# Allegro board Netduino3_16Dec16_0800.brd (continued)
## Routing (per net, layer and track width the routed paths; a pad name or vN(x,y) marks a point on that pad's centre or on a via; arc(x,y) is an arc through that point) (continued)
N199051: length 8.7
  TOP w0.18: R1.2 40.75,41.99 40.88,42.13 40.9,42.13 40.9,42.55 40.31,43.14 39.81,43.14 39.5,43.45 39.1,43.45 38.6,42.95 38.6,40.7 37.7,39.8 Q4.3
N202411: length 25.5
  TOP w0.18: Q8.6 52.65,29.07 53.23,29.65 53.23,36.32 48.65,40.9 v1(42.6,40.9) ; R1.3 40.25,42.4 v1(40.1,42.55)
  BOTTOM w0.18: v1(42.6,40.9) 40.95,42.55 v1(40.1,42.55)
N203046: length 25.7
  TOP w0.18: v1(42.97,40.15) 48.85,40.15 52.65,36.35 52.65,31.95 51.35,30.65 Q8.3 ; R1.4 39.7,41.55 39.33,41.92 39.33,42.17 39.3,42.2 v1(39.3,42.75)
  BOTTOM w0.18: v1(39.3,42.75) 39.69,43.14 41.21,43.14 43.15,41.2 43.15,40.34 v1(42.97,40.15)
N249435: length 34.8
  TOP w0.18: v1(38.3,20.97) 38.85,20.97 39.05,21.17 41.09,21.17 42.53,19.73 U4.48 ; R14.5 v1(30.3,38.97)
  BOTTOM w0.18: v1(30.3,38.97) 30.3,36.14 30.18,36.02 30.18,34.28 30.6,33.86 33.24,31.22 34.2,31.22 34.41,31.01 34.73,30.69 34.73,29.94 33.2,28.41 33.2,20.99 34.97,19.23 37.11,19.23 38.3,20.42 v1(38.3,20.97)
N261857: length 4.3
  TOP w0.18: 27.07,24.75 27.37,25.05 R7.1
  TOP w0.2: 27.07,24.75 Y1.1
  TOP w0.3: C19.1 25.8,24.35 Y1.1

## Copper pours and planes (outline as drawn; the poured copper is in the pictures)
+3.3V on TOP: 22.9,40.3 22.9,37.5 26.7,37.5 27.95,38.75 27.95,40.2 24.35,40.2 24.25,40.3
+3.3V on L3-PWR: 45.75,44 57,32.75 58.5,32.75 60,31.25 60,13.25 59.75,13 59,13 57.75,14.25 39.75,14.25 35.25,9.75 18.25,9.75 17.5,10.5 17.5,17.5 16.25,18.75 16.25,26.75 16.75,27.25 18.25,27.25 18.75,26.75 20.75,26.75 21.25,27.25 21.25,43 20.75,43.5 19.5,43.5 19,44 19,44.25 19.25,44.5 22,44.5 22.5,44
+5.0V on TOP: 17.95,40.7 17.95,42.5 18.65,43.2 20.75,43.2 21.4,42.55 21.4,41.6 19.75,41.6 19.75,40.7
+5.0V on TOP: 16.75,45.6 9.3,45.6 9.3,43 7.25,43 7.25,35 16.75,35
+5.0V on BOTTOM: 0.5,0.5 39.05,0.5 39.05,4.7 40.25,5.9 40.25,8.55 38.4,10.4 38.4,14.85 35.75,17.5 35.75,17.85 28.85,17.85 27.45,19.25 27.45,25.7 27.5,25.7 28.95,27.15 28.25,27.85 28.25,40.25 28.5,40.25 28.5,40.5 28.25,40.75 28.25,49.2 25.45,49.2 23.85,50.8 16.8,50.8 14.8,52.8 0.5,52.8
+5.0V on L2-GND: 16.75,43 7.25,43 7.25,35 16.75,35
+5.0V on L3-PWR: 0.5,0.5 76.25,0.5 77.45,1.7 77.45,51.55 76.2,52.8 0.5,52.8 ; 1 cut-out
GND on TOP: 0.5,0.5 76.25,0.5 77.45,1.7 77.45,51.55 76.2,52.8 0.5,52.8 ; 11 cut-outs
GND on BOTTOM: 0.5,0.5 76.25,0.5 77.45,1.7 77.45,51.55 76.2,52.8 0.5,52.8 ; 2 cut-outs
GND on L2-GND: 0.5,0.5 76.25,0.5 77.45,1.7 77.45,51.55 76.2,52.8 0.5,52.8 ; 1 cut-out
CHASSIS_USB on BOTTOM: 0.5,31.75 4.75,31.75 4.75,28.25 7.25,28.25 7.25,25 4.75,25 4.75,22.75 4,22 4,18.75 0.5,18.75

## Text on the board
Ref Des/Silkscreen Top: 7.5-12V | REV.A | PWR | Power | Digital I/O | Analog In | LED | SCL | SDA | GND | 13 | IOREF | 12 | /RESET | 11 | 3V3 | 10 | 5V | 9 | 8 | 7 | VIN | 6 | 5 | 0 | 4 | 1 | 3 | 2 | www.netduino.com
DIMENSION: FIGURE | SIZE | 0.25 | 0.3302 | 0.5 | 0.8 | 1.0 | 3.2 | 1.0x0.75 | 1.3x0.75 | 3.0x0.8 | 3.5x0.8 | DRILL CHART: TOP to BOTTOM | ALL UNITS ARE IN MILLIMETERS | TOLERANCE | +0.08/-0.08 | +0.1/-0.0 | PLATED | NON-PLATED | QTY | 333 | 61 | 25 | 32 | 6 | 3 | 2 | 1
